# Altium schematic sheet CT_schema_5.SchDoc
size 218 x 258 mm
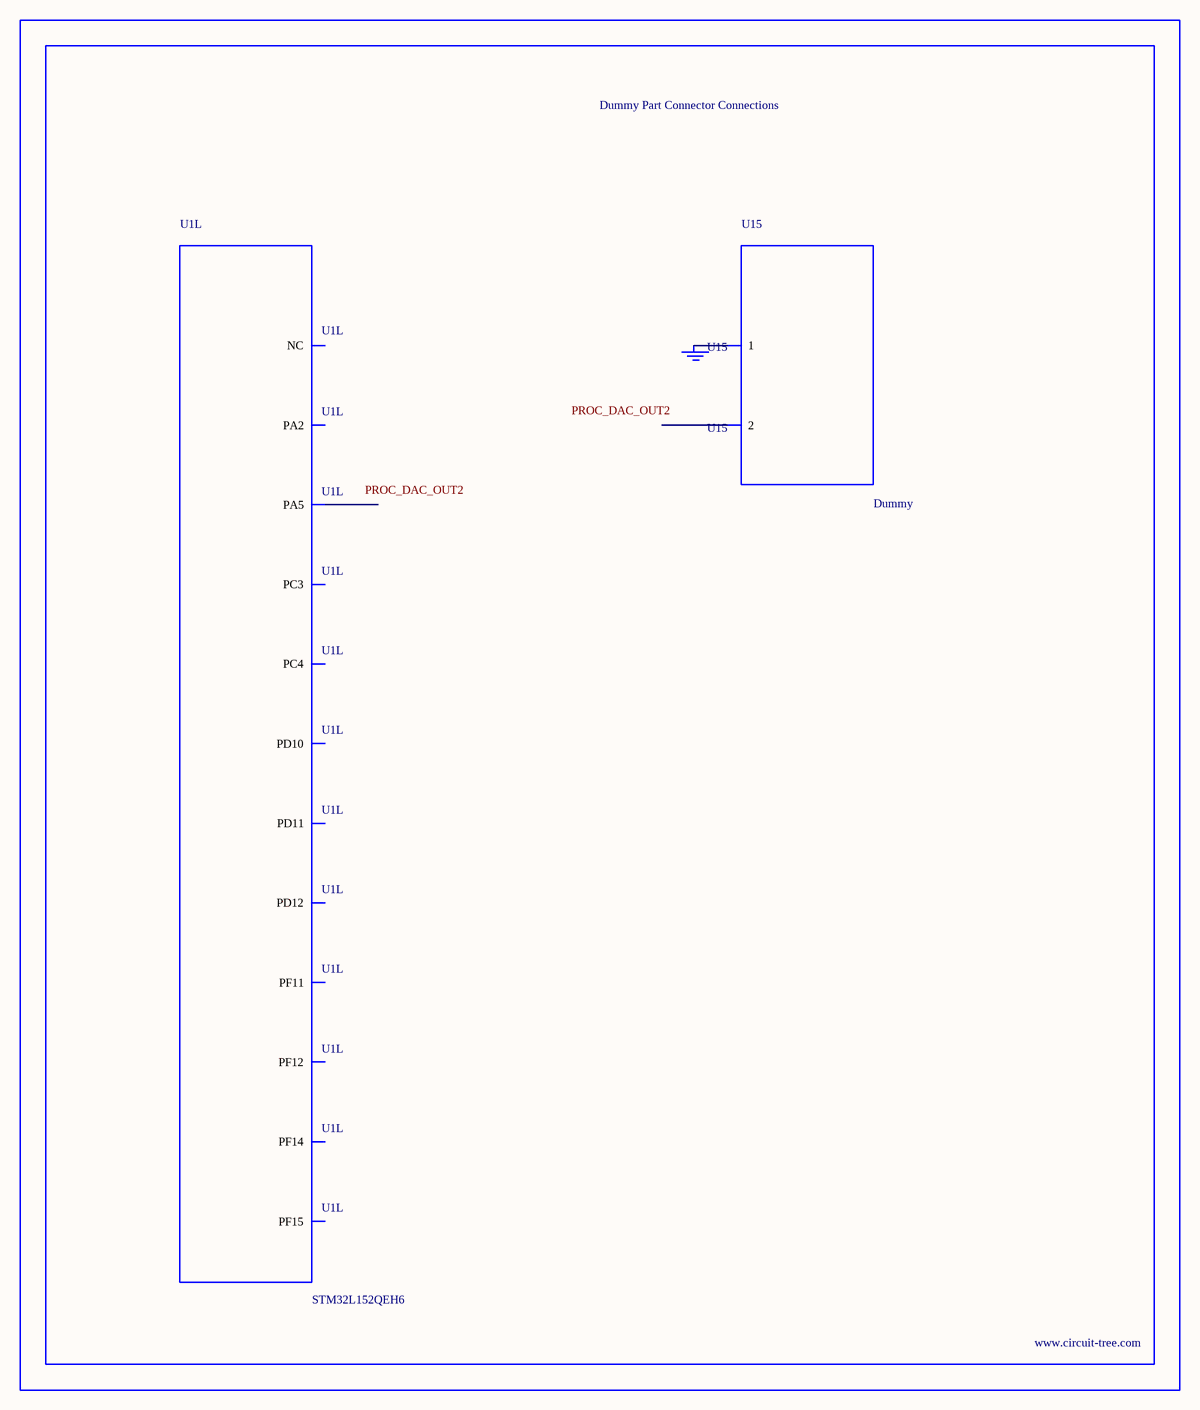
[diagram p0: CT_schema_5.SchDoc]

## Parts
BORDER4  (no value)
GND_INSTANCE_4_0  (no value)
U1  STM32L152QEH6  [UFBGA132]  (part L of 12)
U15  Dummy  [DUMMY_PACKAGE_139]

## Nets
NetGND_INSTANCE_4_0_0: GND_INSTANCE_4_0.0(GND) U15.1

Not connected (* = marked no-connect by the designer): U1 J7(PF12) J8(PF14) J9(PF15) J10(PD12) J11(PD11) J12(PD10) K1(NC) K2(PC3) K3(PA2) K4(PA5) K5(PC4) K6(PF11); U15 2

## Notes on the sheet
- Labels drawn without touching a wire or pin: PROC_DAC_OUT2

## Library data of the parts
BORDER4 = BORDER_PAGE4
GND_INSTANCE_4_0 = GND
